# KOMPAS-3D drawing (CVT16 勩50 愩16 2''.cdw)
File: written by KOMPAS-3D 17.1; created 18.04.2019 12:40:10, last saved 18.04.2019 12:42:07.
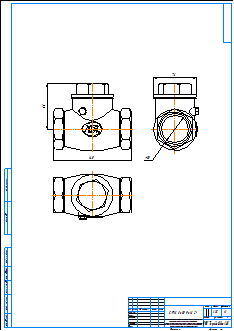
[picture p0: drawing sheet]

Sheet 1: A2, portrait

Title block, sheet 1: name: CVT16 Ду50 Ру16 2''; material: Внимание! Данный продукт является объектом авторского права ООО «Торговый Дом АДЛ». / Запрещается изменение, копирование, распространение / (в том числе путем копирования на другие сайты и ресурсы в Интернете) / или любое иное использование информации и объектов без предварительного / согласия правообладателя (ООО «Торговый Дом АДЛ»).; mass: 1,35; sheets: 1; organisation: ООО "Торговый дом АДЛ"; sheet format: A2

Views: Вид 1, Проекционный вид 2, Проекционный вид 3
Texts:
  user
Dimensions and other numbers on the sheet: 140; 82; 76; 50; 1:1; 1; 1,35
